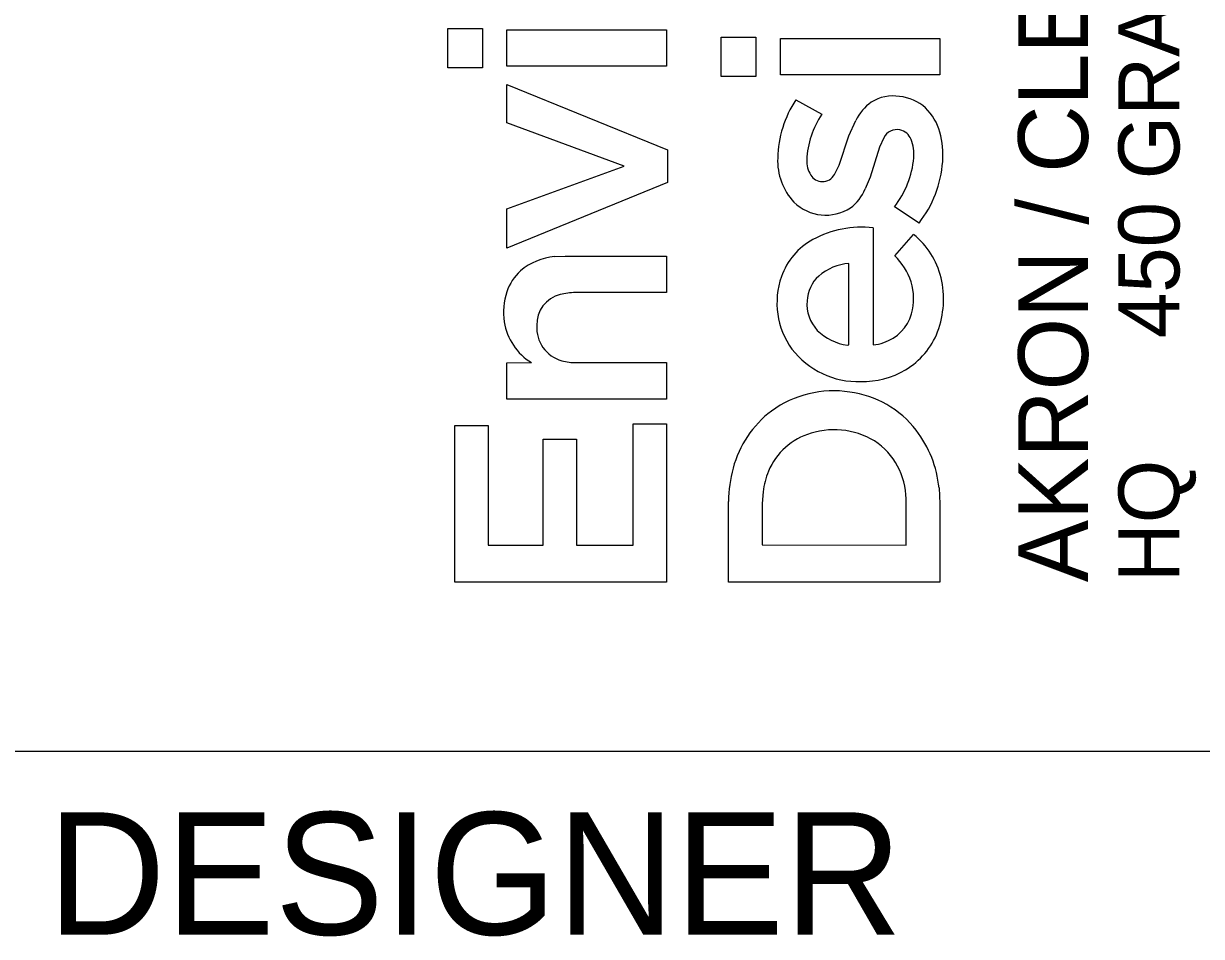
# Model space of a CAD drawing. Extents: x 0 to 63.6, y 0 to 22.
# Drawn here: x 32.03 to 32.993, y 2.849 to 3.594 of the extents above; entities that cross this region are included whole.
import ezdxf

# ---------------------------------------------------------------- set-up
doc = ezdxf.new("R2010")
doc.units = 0
doc.layers.add('SH_Border', color=7, linetype='Continuous')
doc.layers.add('SH_Data', color=7, linetype='Continuous')

msp = doc.modelspace()

# ---------------------------------------------------------------- linework, layer by layer
at = {"layer": 'SH_Border'}
msp.add_line((32, 3), (33.5, 3), dxfattribs=at)
at = {"layer": 'SH_Data'}
for p, q in [((32.37705, 3.55818), (32.37705, 3.59026)), ((32.37705, 3.59026), (32.40543, 3.59026)), ((32.40543, 3.59026), (32.40543, 3.55818)), ((32.42542, 3.55942), (32.42542, 3.58928)), ((32.42542, 3.58928), (32.55571, 3.58928)), ((32.55571, 3.58928), (32.55571, 3.55942)), ((32.60051, 3.55111), (32.60051, 3.58319)), ((32.60051, 3.58319), (32.62889, 3.58319)), ((32.62889, 3.58319), (32.62889, 3.55111)), ((32.64888, 3.55234), (32.64888, 3.5822)), ((32.64888, 3.5822), (32.77917, 3.5822)), ((32.77917, 3.5822), (32.77917, 3.55234)), ((32.40543, 3.55818), (32.37705, 3.55818)), ((32.55571, 3.55942), (32.42542, 3.55942)), ((32.77917, 3.55234), (32.64888, 3.55234)), ((32.42542, 3.51327), (32.42542, 3.5446)), ((32.42542, 3.5446), (32.5567, 3.4913)), ((32.62889, 3.55111), (32.60051, 3.55111)), ((32.66151, 3.53207), (32.68268, 3.52025)), ((32.52117, 3.47798), (32.42542, 3.51327)), ((32.70483, 3.50258), (32.71036, 3.51526)), ((32.69675, 3.47868), (32.70483, 3.50258)), ((32.73342, 3.50101), (32.72985, 3.4933)), ((32.5567, 3.4913), (32.5567, 3.46441)), ((32.72985, 3.4933), (32.72213, 3.46882)), ((32.42542, 3.44294), (32.52117, 3.47798)), ((32.69299, 3.47117), (32.69675, 3.47868)), ((32.72213, 3.46882), (32.71822, 3.45921)), ((32.5567, 3.46441), (32.42542, 3.41086)), ((32.42542, 3.41086), (32.42542, 3.44294)), ((32.76214, 3.43141), (32.74198, 3.44469)), ((32.72453, 3.42747), (32.72463, 3.33195)), ((32.74228, 3.40465), (32.75768, 3.422)), ((32.46439, 3.40397), (32.47289, 3.40443)), ((32.47289, 3.40443), (32.55571, 3.40443)), ((32.55571, 3.40443), (32.55571, 3.37465)), ((32.70489, 3.33182), (32.70489, 3.39834)), ((32.55571, 3.37465), (32.4814, 3.37457)), ((32.70361, 3.33165), (32.70489, 3.33182)), ((32.42542, 3.31728), (32.44552, 3.31733)), ((32.42542, 3.28747), (32.42542, 3.31728)), ((32.48222, 3.31733), (32.55569, 3.31733)), ((32.55569, 3.31733), (32.55571, 3.28756)), ((32.55571, 3.28756), (32.42542, 3.28747)), ((32.38298, 3.13791), (32.38298, 3.26598)), ((32.38298, 3.26598), (32.41012, 3.26598)), ((32.41012, 3.26598), (32.41012, 3.16827)), ((32.52857, 3.16827), (32.52857, 3.26722)), ((32.52857, 3.26722), (32.55571, 3.26722)), ((32.55571, 3.26722), (32.55571, 3.13791)), ((32.45503, 3.16827), (32.45503, 3.25488)), ((32.45503, 3.25488), (32.48218, 3.25488)), ((32.48218, 3.25488), (32.48218, 3.16827)), ((32.77847, 3.21497), (32.77917, 3.2021)), ((32.63465, 3.21178), (32.63407, 3.2023)), ((32.60643, 3.13799), (32.60644, 3.204)), ((32.63407, 3.2023), (32.63407, 3.16838)), ((32.75149, 3.16834), (32.75153, 3.20239)), ((32.77917, 3.2021), (32.77917, 3.138)), ((32.41012, 3.16827), (32.45503, 3.16827)), ((32.48218, 3.16827), (32.52857, 3.16827)), ((32.63407, 3.16838), (32.75149, 3.16834)), ((32.55571, 3.13791), (32.38298, 3.13791)), ((32.77917, 3.138), (32.60643, 3.13799))]:
    msp.add_line(p, q, dxfattribs=at)
for points in [[(32.37705, 3.55818), (32.37705, 3.59026), (32.40543, 3.59026), (32.40543, 3.55818)], [(32.42542, 3.55942), (32.42542, 3.58928), (32.55571, 3.58928), (32.55571, 3.55942)], [(32.60051, 3.55111), (32.60051, 3.58319), (32.62889, 3.58319), (32.62889, 3.55111)], [(32.64888, 3.55234), (32.64888, 3.5822), (32.77917, 3.5822), (32.77917, 3.55234)], [(32.42542, 3.41086), (32.42542, 3.44294), (32.52117, 3.47798), (32.42542, 3.51327), (32.42542, 3.5446), (32.5567, 3.4913), (32.5567, 3.46441)], [(32.38298, 3.13791), (32.38298, 3.26598), (32.41012, 3.26598), (32.41012, 3.16827), (32.45503, 3.16827), (32.45503, 3.25488), (32.48218, 3.25488), (32.48218, 3.16827), (32.52857, 3.16827), (32.52857, 3.26722), (32.55571, 3.26722), (32.55571, 3.13791)]]:
    msp.add_lwpolyline(points, close=True, dxfattribs=at)
for points in [[(32.66151, 3.53207), (32.68268, 3.52025)], [(32.69299, 3.47117), (32.69675, 3.47868), (32.70483, 3.50258), (32.71036, 3.51526)], [(32.73342, 3.50101), (32.72985, 3.4933), (32.72213, 3.46882), (32.71822, 3.45921)], [(32.76214, 3.43141), (32.74198, 3.44469)], [(32.72453, 3.42747), (32.72463, 3.33195)], [(32.74228, 3.40465), (32.75768, 3.422)], [(32.46439, 3.40397), (32.47289, 3.40443), (32.55571, 3.40443), (32.55571, 3.37465), (32.4814, 3.37457)], [(32.70361, 3.33165), (32.70489, 3.33182), (32.70489, 3.39834)], [(32.42542, 3.28747), (32.42542, 3.31728), (32.44552, 3.31733)], [(32.48222, 3.31733), (32.55569, 3.31733), (32.55571, 3.28756), (32.42542, 3.28747)], [(32.77847, 3.21497), (32.77917, 3.2021), (32.77917, 3.138), (32.60643, 3.13799)], [(32.63465, 3.21178), (32.63407, 3.2023), (32.63407, 3.16838), (32.75149, 3.16834), (32.75153, 3.20239)], [(32.60643, 3.13799), (32.60644, 3.204)]]:
    msp.add_lwpolyline(points, dxfattribs=at)
for centre, radius, start, end in [((32.73636, 3.48258), 0.08973, 146.53104, 178.7571), ((32.73636, 3.48258), 0.08973, 146.53104, 178.7571), ((32.7406, 3.5026), 0.03263, 80.17192, 122.51969), ((32.7406, 3.5026), 0.03263, 80.17192, 122.51969), ((32.74278, 3.49824), 0.03667, 47.79344, 84.68918), ((32.74278, 3.49824), 0.03667, 47.79344, 84.68918), ((32.74661, 3.49713), 0.04053, 125.51182, 153.41595), ((32.74661, 3.49713), 0.04053, 125.51182, 153.41595), ((32.73788, 3.4946), 0.04267, 14.9966, 46.20632), ((32.73788, 3.4946), 0.04267, 14.9966, 46.20632), ((32.74519, 3.4789), 0.07495, 146.51121, 176.91007), ((32.74519, 3.4789), 0.07495, 146.51121, 176.91007), ((32.74384, 3.49631), 0.01143, 76.66094, 155.7053), ((32.74384, 3.49631), 0.01143, 76.66094, 155.7053), ((32.74397, 3.49511), 0.01256, 21.5098, 78.52618), ((32.74397, 3.49511), 0.01256, 21.5098, 78.52618), ((32.71044, 3.48674), 0.07121, 355.83062, 15.39138), ((32.71044, 3.48674), 0.07121, 355.83062, 15.39138), ((32.72592, 3.48766), 0.03209, 354.57264, 22.06805), ((32.72592, 3.48766), 0.03209, 354.57264, 22.06805), ((32.69666, 3.48238), 0.05005, 177.53659, 222.79318), ((32.69666, 3.48238), 0.05005, 177.53659, 222.79318), ((32.68248, 3.49149), 0.0757, 321.81101, 354.79685), ((32.68248, 3.49149), 0.0757, 321.81101, 354.79685), ((32.6931, 3.48233), 0.02276, 178.47474, 211.08679), ((32.6931, 3.48233), 0.02276, 178.47474, 211.08679), ((32.68952, 3.4882), 0.09219, 321.9777, 355.87384), ((32.68952, 3.4882), 0.09219, 321.9777, 355.87384), ((32.68331, 3.4767), 0.01148, 212.23676, 268.37769), ((32.68331, 3.4767), 0.01148, 212.23676, 268.37769), ((32.68342, 3.47589), 0.01067, 267.71603, 333.73375), ((32.68342, 3.47589), 0.01067, 267.71603, 333.73375), ((32.68098, 3.4758), 0.04077, 308.08772, 335.98736), ((32.68098, 3.4758), 0.04077, 308.08772, 335.98736), ((32.68599, 3.47535), 0.0375, 225.98539, 302.47965), ((32.68599, 3.47535), 0.0375, 225.98539, 302.47965), ((32.7152, 3.34414), 0.08384, 83.61499, 118.28755), ((32.7152, 3.34414), 0.08384, 83.61499, 118.28755), ((32.70239, 3.36906), 0.05583, 118.83082, 160.62438), ((32.70239, 3.36906), 0.05583, 118.83082, 160.62438), ((32.71744, 3.37167), 0.06443, 13.53365, 51.36148), ((32.71744, 3.37167), 0.06443, 13.53365, 51.36148), ((32.46871, 3.35428), 0.04988, 94.96958, 130.22249), ((32.46871, 3.35428), 0.04988, 94.96958, 130.22249), ((32.70785, 3.35609), 0.04235, 94.00805, 130.88169), ((32.70785, 3.35609), 0.04235, 94.00805, 130.88169), ((32.70378, 3.36556), 0.05486, 19.03571, 45.44059), ((32.70378, 3.36556), 0.05486, 19.03571, 45.44059), ((32.46348, 3.36263), 0.04015, 132.22192, 161.68183), ((32.46348, 3.36263), 0.04015, 132.22192, 161.68183), ((32.70048, 3.36628), 0.02985, 132.98507, 177.179), ((32.70048, 3.36628), 0.02985, 132.98507, 177.179), ((32.71041, 3.36612), 0.06437, 160.52012, 215.78311), ((32.71041, 3.36612), 0.06437, 160.52012, 215.78311), ((32.71069, 3.3697), 0.047, 344.60586, 17.007), ((32.71069, 3.3697), 0.047, 344.60586, 17.007), ((32.70635, 3.36921), 0.07579, 339.3542, 13.37853), ((32.70635, 3.36921), 0.07579, 339.3542, 13.37853), ((32.47872, 3.35819), 0.05601, 162.27355, 187.79185), ((32.47872, 3.35819), 0.05601, 162.27355, 187.79185), ((32.47482, 3.34867), 0.02498, 103.68646, 182.21874), ((32.47482, 3.34867), 0.02498, 103.68646, 182.21874), ((32.48108, 3.32856), 0.04601, 89.60494, 105.3284), ((32.48108, 3.32856), 0.04601, 89.60494, 105.3284), ((32.7017, 3.36503), 0.03115, 175.00126, 223.28301), ((32.7017, 3.36503), 0.03115, 175.00126, 223.28301), ((32.47026, 3.35802), 0.04762, 188.96199, 238.70369), ((32.47026, 3.35802), 0.04762, 188.96199, 238.70369), ((32.7224, 3.36715), 0.03504, 288.00773, 343.55078), ((32.7224, 3.36715), 0.03504, 288.00773, 343.55078), ((32.47735, 3.34558), 0.02756, 175.58538, 255.14386), ((32.47735, 3.34558), 0.02756, 175.58538, 255.14386), ((32.70891, 3.37363), 0.04231, 225.06188, 262.79738), ((32.70891, 3.37363), 0.04231, 225.06188, 262.79738), ((32.71894, 3.3652), 0.0626, 300.94269, 338.73225), ((32.71894, 3.3652), 0.0626, 300.94269, 338.73225), ((32.72474, 3.35216), 0.02021, 269.7003, 294.8711), ((32.72474, 3.35216), 0.02021, 269.7003, 294.8711), ((32.71253, 3.37054), 0.06872, 217.74516, 271.65431), ((32.71253, 3.37054), 0.06872, 217.74516, 271.65431), ((32.48183, 3.35948), 0.04215, 254.09162, 270.52835), ((32.48183, 3.35948), 0.04215, 254.09162, 270.52835), ((32.71549, 3.37241), 0.07056, 269.20477, 300.33412), ((32.71549, 3.37241), 0.07056, 269.20477, 300.33412), ((32.69229, 3.20792), 0.08641, 81.19402, 125.99844), ((32.69229, 3.20792), 0.08641, 81.19402, 125.99844), ((32.69458, 3.21132), 0.08272, 37.85208, 82.40204), ((32.69458, 3.21132), 0.08272, 37.85208, 82.40204), ((32.69387, 3.20893), 0.08654, 127.23621, 165.14796), ((32.69387, 3.20893), 0.08654, 127.23621, 165.14796), ((32.69279, 3.19862), 0.06389, 55.67272, 107.20935), ((32.69279, 3.19862), 0.06389, 55.67272, 107.20935), ((32.68893, 3.20782), 0.05398, 106.18808, 157.38609), ((32.68893, 3.20782), 0.05398, 106.18808, 157.38609), ((32.68586, 3.20567), 0.09308, 5.73329, 37.30396), ((32.68586, 3.20567), 0.09308, 5.73329, 37.30396), ((32.69291, 3.20499), 0.05867, 357.46616, 52.26647), ((32.69291, 3.20499), 0.05867, 357.46616, 52.26647), ((32.71426, 3.20281), 0.10783, 164.7861, 179.37039), ((32.71426, 3.20281), 0.10783, 164.7861, 179.37039), ((32.69829, 3.20389), 0.06412, 157.35705, 172.92755), ((32.69829, 3.20389), 0.06412, 157.35705, 172.92755)]:
    msp.add_arc(centre, radius, start, end, dxfattribs=at)

# ---------------------------------------------------------------- texts
for s, height, p in [('450 GRANT ST., AKRON, OH  44311', 0.0498462, (32.97489, 3.33738)), ('AKRON / CLEVELAND / COLUMBUS', 0.056969, (32.90012, 3.138)), ('HQ ', 0.049846, (32.97489, 3.138))]:
    msp.add_text(s, height=height, rotation=90, dxfattribs=at).set_placement(p)
msp.add_text('DESIGNER', height=0.1, dxfattribs=at).set_placement((32.05, 2.85))

doc.saveas('drawing.dxf')
